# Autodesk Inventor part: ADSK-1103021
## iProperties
Shininess: 41.0
Length Units: 11272
Angle Units: 11279
Time Units: 11290
Mass Units: 11286
Length Display Precision: 4
Angle Display Precision: 2
Compacted: True
Created: 2000-09
Part Number: ADSK-1103021
Document SubType Name: Modeling
Description: SLIDE
Mass: 1.8504 g
Surface Area: 11.013 cm^2
Volume: 0.682806 cm^3
Density: 2.71 g/cm^3
Material: Aluminum-6061
Density: 0.0
Volumn: 0.0
Area: 0.0
PropertySet Name: Model Information
Control State: 0
Master: False
Checked Out: False
Author: Autodesk, Inc.
